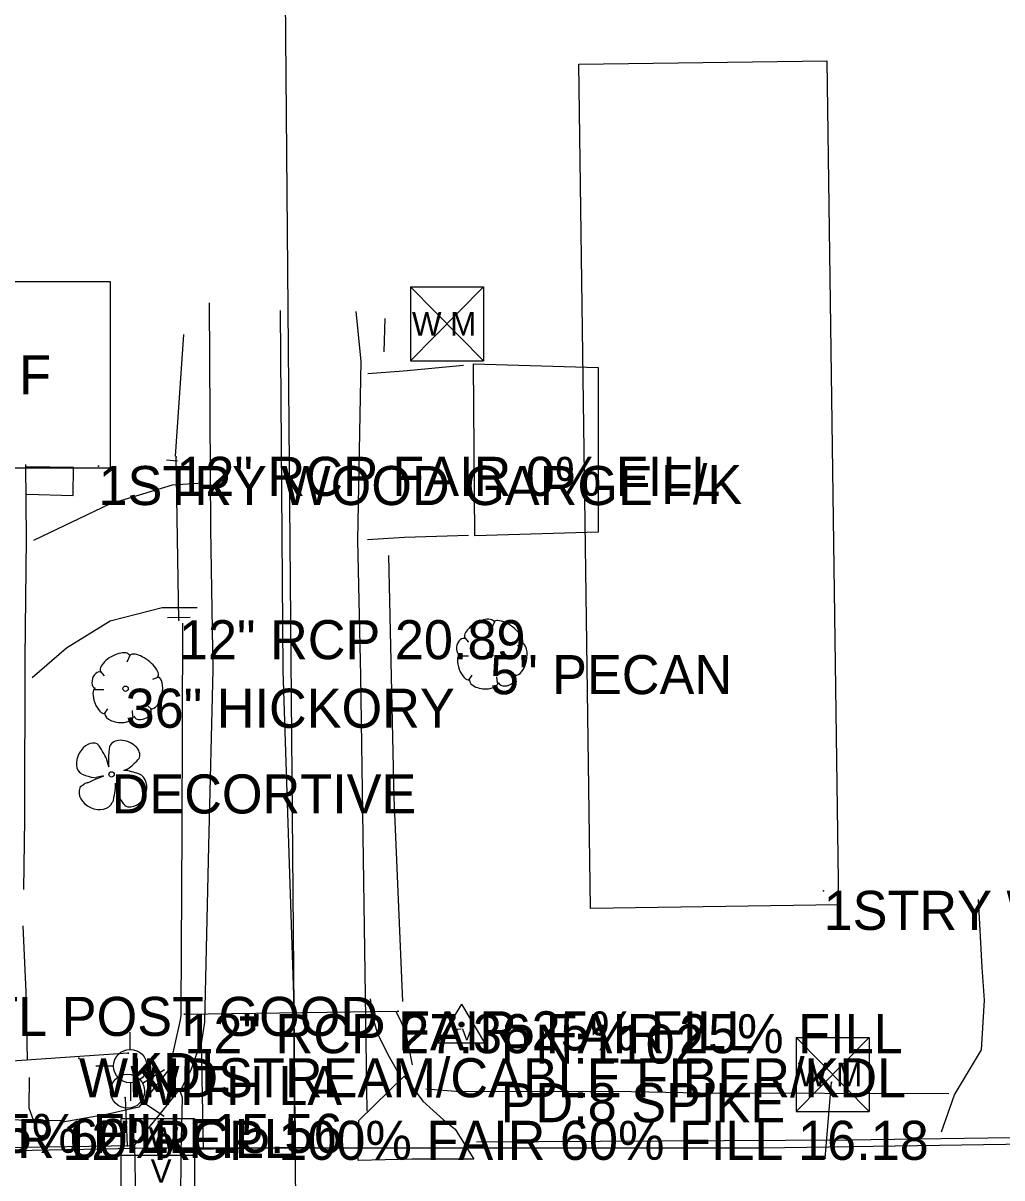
# Model space of a CAD drawing. Extents: x 1304270 to 1306561, y 1876019 to 1876752.
# Drawn here: x 1305592.5 to 1305717.8, y 1876418.6 to 1876566.4 of the extents above; entities that cross this region are included whole.
import ezdxf

# ---------------------------------------------------------------- set-up
doc = ezdxf.new("R2010")
doc.units = 0
for name, color, linetype in [('S_BUILDING', 7, 'Continuous'), ('S_BUILDING_ANNOT', 7, 'Continuous'), ('S_CROSS_DRAIN', 7, 'Continuous'), ('S_CROSS_DRAIN_ANNOT', 7, 'Continuous'), ('S_DITCHLINE', 7, 'Continuous'), ('S_DRG_PT_SYM', 7, 'Continuous'), ('S_DRIVEWAY', 7, 'Continuous'), ('S_EDGE_CONCRETE', 7, 'Continuous'), ('S_EDGE_PAVEMENT', 7, 'Continuous'), ('S_FENCE_ANNOT', 7, 'Continuous'), ('S_FIBER_OPTIC_CABLE', 7, 'Continuous'), ('S_FIBER_OPTIC_CABLE_ANNOT', 7, 'Continuous'), ('S_HEADWALL', 7, 'Continuous'), ('S_MSC_PT_SYM', 7, 'Continuous'), ('S_PAVEMENT_CROWN', 7, 'Continuous'), ('S_SANITARY_SEWER', 7, 'Continuous'), ('S_SECONDARY_CTL', 7, 'Continuous'), ('S_SECONDARY_CTL_ANNOT', 7, 'Continuous'), ('S_SHOULDER', 7, 'Continuous'), ('S_SIDE_DRAIN', 7, 'Continuous'), ('S_SIDE_DRAIN_ANNOT', 7, 'Continuous'), ('S_STR_PT_SYM', 7, 'Continuous'), ('S_SURVEY_TEXT_ANNOT', 7, 'Continuous'), ('S_TREE', 7, 'Continuous'), ('S_TREE_ANNOT', 7, 'Continuous'), ('S_UTILITY_POLE', 7, 'Continuous'), ('S_UTILITY_POLE_ANNOT', 7, 'Continuous'), ('S_UTL_PT_SYM', 7, 'Continuous'), ('S_WATER_UTILITIES', 7, 'Continuous')]:
    doc.layers.add(name, color=color, linetype=linetype)

msp = doc.modelspace()

# ---------------------------------------------------------------- linework, layer by layer
at = {"layer": 'S_BUILDING'}
for points in [[(1305695.38, 1876561.55), (1305696.88, 1876453.53), (1305665.14, 1876453.09), (1305663.64, 1876561.11)], [(1305583.2, 1876509.43), (1305583.21, 1876533.31), (1305603.68, 1876533.3), (1305603.67, 1876509.42)]]:
    msp.add_lwpolyline(points, close=True, dxfattribs=at)
at = {"layer": 'S_CROSS_DRAIN'}
msp.add_line((1305613.16, 1876439.55), (1305640.51, 1876439.91), dxfattribs=at)
at = {"layer": 'S_DITCHLINE'}
for points in [[(1305638.83, 1876528.57), (1305638.7, 1876524.33)], [(1305613.05, 1876526.51), (1305612, 1876510.94)], [(1305641.11, 1876441.17), (1305640.57, 1876454.2), (1305640.03, 1876467.24), (1305639.68, 1876482.75), (1305639.32, 1876498.26)], [(1305612.93, 1876489.58), (1305612.88, 1876476.34), (1305612.84, 1876463.1), (1305612.69, 1876440.08), (1305612.73, 1876439.33), (1305612.59, 1876438.62), (1305611.2, 1876432.5), (1305607.35, 1876427.64), (1305603.4, 1876426.75), (1305597.6, 1876425.74)], [(1305642.36, 1876433.06), (1305641.55, 1876437.08), (1305640.82, 1876438.78), (1305640.27, 1876439.83)]]:
    msp.add_lwpolyline(points, dxfattribs=at)
at = {"layer": 'S_DRG_PT_SYM'}
for points in [[(1305612.13, 1876510.88), (1305612.13, 1876510.93), (1305612.13, 1876510.88), (1305612.08, 1876510.88), (1305612.13, 1876510.88), (1305612.13, 1876510.83), (1305612.13, 1876510.88), (1305612.18, 1876510.88)], [(1305612.46, 1876489.97), (1305612.46, 1876490.02), (1305612.46, 1876489.97), (1305612.41, 1876489.97), (1305612.46, 1876489.97), (1305612.46, 1876489.92), (1305612.46, 1876489.97), (1305612.51, 1876489.97)], [(1305613.16, 1876439.55), (1305613.16, 1876439.6), (1305613.16, 1876439.55), (1305613.11, 1876439.55), (1305613.16, 1876439.55), (1305613.16, 1876439.5), (1305613.16, 1876439.55), (1305613.21, 1876439.55)], [(1305640.51, 1876439.91), (1305640.51, 1876439.96), (1305640.51, 1876439.91), (1305640.45, 1876439.91), (1305640.51, 1876439.91), (1305640.51, 1876439.86), (1305640.51, 1876439.91), (1305640.55, 1876439.91)], [(1305597.54, 1876425.9), (1305597.54, 1876425.95), (1305597.54, 1876425.9), (1305597.49, 1876425.9), (1305597.54, 1876425.9), (1305597.54, 1876425.85), (1305597.54, 1876425.9), (1305597.59, 1876425.9)]]:
    msp.add_lwpolyline(points, dxfattribs=at)
at = {"layer": 'S_DRIVEWAY'}
for points in [[(1305636.66, 1876521.54), (1305641.19, 1876521.88), (1305648.89, 1876522.59)], [(1305592.81, 1876509.9), (1305592.9, 1876500.39), (1305592.75, 1876485.12), (1305592.69, 1876464.5), (1305592.57, 1876455.51)], [(1305615.59, 1876507.51), (1305611.6, 1876507.24), (1305603.57, 1876504.81), (1305593.84, 1876500.18)], [(1305649.51, 1876500.8), (1305641.33, 1876500.55), (1305636.59, 1876500.27)], [(1305593.7, 1876482.62), (1305598.08, 1876486.44), (1305603.65, 1876489.87), (1305610.31, 1876491.59), (1305614.82, 1876491.57)], [(1305710.05, 1876424.49), (1305711.72, 1876429.21), (1305715.2, 1876434.98), (1305715.56, 1876441.35), (1305715.25, 1876445.5), (1305714.78, 1876454.23)], [(1305593.07, 1876433.69), (1305592.9, 1876442.34), (1305592.55, 1876450.85)], [(1305593.28, 1876431.42), (1305593.25, 1876427.54), (1305594.59, 1876423.91)]]:
    msp.add_lwpolyline(points, dxfattribs=at)
msp.add_lwpolyline([(1305650.18, 1876522.79), (1305666.13, 1876522.32), (1305666.14, 1876501.23), (1305650.34, 1876500.78)], close=True, dxfattribs=at)
at = {"layer": 'S_EDGE_CONCRETE'}
for points in [[(1305592.99, 1876506.09), (1305598.91, 1876505.92), (1305598.98, 1876509.5), (1305592.97, 1876509.58)], [(1305606.95, 1876415.73), (1305606.84, 1876422.83), (1305609.75, 1876426.4), (1305612.13, 1876429.33), (1305612.55, 1876429.88), (1305612.9, 1876428.9), (1305612.8, 1876425.2), (1305612.7, 1876421.97), (1305612.68, 1876415.16)]]:
    msp.add_lwpolyline(points, dxfattribs=at)
msp.add_lwpolyline([(1305650.19, 1876420.99), (1305642.3, 1876420.97), (1305635.39, 1876420.81), (1305635.48, 1876425.93), (1305641.29, 1876431.6), (1305643.69, 1876428.4), (1305646.34, 1876426.01), (1305647.82, 1876424.84)], close=True, dxfattribs=at)
at = {"layer": 'S_EDGE_PAVEMENT'}
for points in [[(1305615.62, 1876422.51), (1305615.36, 1876435.81), (1305615.78, 1876438.51), (1305616.3, 1876461.07), (1305616.83, 1876483.63), (1305616.55, 1876501.66), (1305616.47, 1876516.12), (1305616.39, 1876530.58)], [(1305636.55, 1876427.14), (1305636.35, 1876441.93), (1305636.05, 1876462.38), (1305635.75, 1876482.84), (1305635.35, 1876500.2), (1305635.78, 1876523.1), (1305635.13, 1876529.49)], [(1305640.77, 1876431.64), (1305639.41, 1876434.05), (1305637.97, 1876436.91), (1305637.33, 1876439), (1305636.97, 1876441.52)], [(1305612.66, 1876429.78), (1305614.03, 1876432.44), (1305615.18, 1876435.69)], [(1305650.55, 1876423.21), (1305674.32, 1876423.35), (1305698.09, 1876423.48), (1305721.97, 1876423.8), (1305745.85, 1876424.12), (1305770.29, 1876424.67), (1305794.74, 1876425.23), (1305811.42, 1876425.85), (1305825.07, 1876426.72), (1305843.96, 1876426.78), (1305860.03, 1876426.98), (1305876.09, 1876427.18), (1305883.24, 1876427.59), (1305898.06, 1876427.36), (1305904.05, 1876427.05), (1305918.23, 1876426.76), (1305933.32, 1876426.78)], [(1305388.38, 1876420.94), (1305412.9, 1876420.99), (1305437.42, 1876421.04), (1305451.62, 1876420.93), (1305465.15, 1876420.97), (1305478.67, 1876421.01), (1305492.19, 1876421.05), (1305505.71, 1876421.09), (1305520.11, 1876421.2), (1305523.54, 1876421.95), (1305534.76, 1876421.53), (1305559.32, 1876421.96), (1305583.88, 1876422.38), (1305606.66, 1876422.73)], [(1305612.81, 1876422.22), (1305627.2, 1876422.52), (1305635.24, 1876422.4)]]:
    msp.add_lwpolyline(points, dxfattribs=at)
at = {"layer": 'S_FIBER_OPTIC_CABLE'}
msp.add_line((1305605.99, 1876434.57), (1305581.98, 1876432.88), dxfattribs=at)
at = {"layer": 'S_HEADWALL'}
for points in [[(1305612.27, 1876510.3), (1305610.86, 1876510.44)], [(1305613.91, 1876490.33), (1305611, 1876490.27)]]:
    msp.add_lwpolyline(points, dxfattribs=at)
at = {"layer": 'S_MSC_PT_SYM'}
for points in [[(1305602.17, 1876509.7), (1305602.17, 1876509.75), (1305602.17, 1876509.7), (1305602.12, 1876509.7), (1305602.17, 1876509.7), (1305602.17, 1876509.65), (1305602.17, 1876509.7), (1305602.22, 1876509.7)], [(1305599.66, 1876433.91), (1305599.66, 1876433.96), (1305599.66, 1876433.91), (1305599.61, 1876433.91), (1305599.66, 1876433.91), (1305599.66, 1876433.86), (1305599.66, 1876433.91), (1305599.71, 1876433.91)]]:
    msp.add_lwpolyline(points, dxfattribs=at)
at = {"layer": 'S_PAVEMENT_CROWN'}
msp.add_lwpolyline([(1305627.31, 1876423.22), (1305627.18, 1876441.92), (1305626.49, 1876462.73), (1305625.8, 1876483.54), (1305625.64, 1876506.57), (1305625.48, 1876529.6)], dxfattribs=at)
at = {"layer": 'S_SANITARY_SEWER'}
msp.add_line((1305627.46, 1876413.95), (1305625.83, 1876600.63), dxfattribs=at)
at = {"layer": 'S_SECONDARY_CTL'}
for p, q in [((1305648.63, 1876440.83), (1305645.62, 1876435.88)), ((1305648.63, 1876440.83), (1305651.58, 1876435.88)), ((1305645.62, 1876435.88), (1305651.58, 1876435.88))]:
    msp.add_line(p, q, dxfattribs=at)
for radius in [0.311, 0.183, 0.103]:
    msp.add_circle((1305648.63, 1876438.22), radius, dxfattribs=at)
at = {"layer": 'S_SHOULDER'}
msp.add_lwpolyline([(1305644.05, 1876429.98), (1305648.45, 1876429.64), (1305668.23, 1876429.67), (1305679.16, 1876429.46), (1305695.09, 1876429.42), (1305711.02, 1876429.38)], dxfattribs=at)
at = {"layer": 'S_SIDE_DRAIN'}
for p, q in [((1305612.46, 1876489.97), (1305612.13, 1876510.88)), ((1305597.54, 1876425.9), (1305581.35, 1876426.14))]:
    msp.add_line(p, q, dxfattribs=at)
at = {"layer": 'S_STR_PT_SYM'}
msp.add_lwpolyline([(1305694.97, 1876455.33), (1305694.97, 1876455.38), (1305694.97, 1876455.33), (1305694.92, 1876455.33), (1305694.97, 1876455.33), (1305694.97, 1876455.28), (1305694.97, 1876455.33), (1305695.02, 1876455.33)], dxfattribs=at)
at = {"layer": 'S_TREE'}
for p, q in [((1305652.84, 1876489.74), (1305652.45, 1876488.89)), ((1305649.04, 1876487.73), (1305649.54, 1876487.15)), ((1305656.4, 1876486.95), (1305655.74, 1876486.68)), ((1305606.2, 1876485.44), (1305605.81, 1876484.59)), ((1305648.38, 1876485.4), (1305649.51, 1876485.4)), ((1305602.4, 1876483.43), (1305602.9, 1876482.85)), ((1305655.63, 1876482.85), (1305655.16, 1876483.27)), ((1305609.76, 1876482.65), (1305609.1, 1876482.38)), ((1305649.54, 1876482.23), (1305650.01, 1876482.92)), ((1305653.23, 1876481.96), (1305653.15, 1876482.73)), ((1305601.74, 1876481.1), (1305602.86, 1876481.1)), ((1305608.99, 1876478.55), (1305608.52, 1876478.97)), ((1305602.9, 1876477.93), (1305603.37, 1876478.62)), ((1305606.58, 1876477.65), (1305606.51, 1876478.43)), ((1305603.48, 1876471.21), (1305603.24, 1876472.1)), ((1305602.83, 1876470.05), (1305601.86, 1876469.83)), ((1305605.43, 1876470.75), (1305605.81, 1876470.91)), ((1305604.37, 1876469.12), (1305604.45, 1876468.68))]:
    msp.add_line(p, q, dxfattribs=at)
for centre in [(1305652.28, 1876485.5), (1305605.64, 1876481.2), (1305603.85, 1876470.23)]:
    msp.add_circle(centre, 0.341, dxfattribs=at)
for centre, major_axis, ratio, start_param, end_param in [((1305650.94, 1876488.7), (1.86, 1.08), 0.471018, 0, 3.141593), ((1305654.6, 1876488.38), (-1.81, 1.36), 0.405113, 3.141593, 6.283186), ((1305648.71, 1876486.59), (0.31, 1.03), 0.646762, 0, 3.141593), ((1305655.95, 1876484.97), (0.46, 2.04), 0.482994, 3.141593, 6.283185), ((1305604.3, 1876484.4), (1.86, 1.08), 0.471018, 0, 3.141593), ((1305607.96, 1876484.08), (-1.81, 1.36), 0.405113, 3.141593, 6.283186), ((1305649.01, 1876483.94), (-0.61, 1.6), 0.420543, 6.283185, 9.424777), ((1305602.07, 1876482.29), (0.31, 1.03), 0.646762, 0, 3.141593), ((1305609.31, 1876480.67), (0.46, 2.04), 0.482994, 3.141593, 6.283185), ((1305651.48, 1876482.16), (-1.83, 0.19), 0.529943, 0, 3.141593), ((1305654.43, 1876482.45), (1.09, 0.46), 0.711534, 3.141592, 6.283185), ((1305602.37, 1876479.64), (-0.61, 1.6), 0.420543, 6.283185, 9.424777), ((1305604.83, 1876477.85), (-1.83, 0.19), 0.529943, 0, 3.141593), ((1305607.79, 1876478.15), (1.09, 0.46), 0.711534, 3.141592, 6.283185), ((1305600.96, 1876472.25), (-1.03, -1.88), 0.662338, 3.141593, 6.283185), ((1305605.51, 1876473.12), (1.89, -0.74), 0.673998, 0, 3.141593), ((1305602.62, 1876473.12), (0.62, -1.01), 0.083512, 0, 3.141593), ((1305603.55, 1876472.54), (-0.07, -1.33), 0.068203, 3.141593, 6.283185), ((1305606.61, 1876471.64), (-0.798, -0.73), 0.092159, 0, 3.141593), ((1305600.9, 1876470.1), (0.964, -0.267), 0.113563, 3.141593, 6.283185), ((1305601.8, 1876469.61), (1.04, 0.44), 0.002756, 3.141593, 6.283185), ((1305606.39, 1876470.52), (0.96, -0.23), 0.056001, 0, 3.141593), ((1305606.47, 1876468.25), (0.88, 2.05), 0.81717, 3.141593, 6.283185), ((1305601.87, 1876467.57), (2.07, -0.93), 0.760068, 3.141593, 6.283185), ((1305600.28, 1876468.83), (0.477, 0.328), 0.136309, 0, 3.141593), ((1305604.13, 1876467.95), (0.19, 1.31), 0.114148, 3.141593, 5.822668), ((1305604.7, 1876467.91), (0.254, -0.771), 0.051603, 3.141593, 6.283185), ((1305605.28, 1876466.67), (-0.321, 0.467), 0.094289, 0, 3.141593)]:
    msp.add_ellipse(centre, major_axis=major_axis, ratio=ratio, start_param=start_param, end_param=end_param, dxfattribs=at)
at = {"layer": 'S_UTILITY_POLE'}
for p, q in [((1305606.24, 1876435.01), (1305606.24, 1876437.25)), ((1305604.15, 1876432.88), (1305601.82, 1876432.88)), ((1305606.32, 1876428.46), (1305606.32, 1876430.78))]:
    msp.add_line(p, q, dxfattribs=at)
msp.add_circle((1305606.24, 1876432.9), 2.13, dxfattribs=at)
at = {"layer": 'S_UTL_PT_SYM'}
for points in [[(1305605.99, 1876434.57), (1305605.99, 1876434.62), (1305605.99, 1876434.57), (1305605.94, 1876434.57), (1305605.99, 1876434.57), (1305605.99, 1876434.52), (1305605.99, 1876434.57), (1305606.04, 1876434.57)], [(1305695.99, 1876430.82), (1305695.99, 1876430.87), (1305695.99, 1876430.82), (1305695.94, 1876430.82), (1305695.99, 1876430.82), (1305695.99, 1876430.77), (1305695.99, 1876430.82), (1305696.04, 1876430.82)], [(1305605.6, 1876428.86), (1305605.6, 1876428.91), (1305605.6, 1876428.86), (1305605.55, 1876428.86), (1305605.6, 1876428.86), (1305605.6, 1876428.81), (1305605.6, 1876428.86), (1305605.65, 1876428.86)], [(1305605.86, 1876422.69), (1305605.86, 1876422.74), (1305605.86, 1876422.69), (1305605.81, 1876422.69), (1305605.86, 1876422.69), (1305605.86, 1876422.64), (1305605.86, 1876422.69), (1305605.91, 1876422.69)], [(1305609.14, 1876422.38), (1305609.14, 1876422.43), (1305609.14, 1876422.38), (1305609.09, 1876422.38), (1305609.14, 1876422.38), (1305609.14, 1876422.33), (1305609.14, 1876422.38), (1305609.19, 1876422.38)], [(1305687.16, 1876422.39), (1305687.16, 1876422.44), (1305687.16, 1876422.39), (1305687.11, 1876422.39), (1305687.16, 1876422.39), (1305687.16, 1876422.34), (1305687.16, 1876422.39), (1305687.21, 1876422.39)], [(1305695.18, 1876421.13), (1305695.18, 1876421.18), (1305695.18, 1876421.13), (1305695.13, 1876421.13), (1305695.18, 1876421.13), (1305695.18, 1876421.08), (1305695.18, 1876421.13), (1305695.23, 1876421.13)]]:
    msp.add_lwpolyline(points, dxfattribs=at)
at = {"layer": 'S_WATER_UTILITIES'}
for p, q in [((1305642.09, 1876532.64), (1305651.43, 1876532.64)), ((1305642.09, 1876532.64), (1305642.09, 1876523.14)), ((1305642.09, 1876532.64), (1305651.43, 1876523.14)), ((1305651.43, 1876532.64), (1305642.09, 1876523.14)), ((1305651.43, 1876532.64), (1305651.43, 1876523.14)), ((1305642.09, 1876523.14), (1305651.43, 1876523.14)), ((1305691.46, 1876436.56), (1305700.8, 1876436.56)), ((1305691.46, 1876436.56), (1305691.46, 1876427.07)), ((1305691.46, 1876436.56), (1305700.8, 1876427.07)), ((1305700.8, 1876436.56), (1305691.46, 1876427.07)), ((1305700.8, 1876436.56), (1305700.8, 1876427.07)), ((1305607.8, 1876430.73), (1305610.63, 1876432.46)), ((1305695.18, 1876421.13), (1305695.99, 1876430.82)), ((1305605.6, 1876428.86), (1305605.86, 1876422.69)), ((1305607.68, 1876428.42), (1305610.59, 1876426.5)), ((1305691.46, 1876427.07), (1305700.8, 1876427.07)), ((1305605.07, 1876426.2), (1305614.48, 1876426.2)), ((1305605.07, 1876416.79), (1305605.07, 1876426.2)), ((1305614.48, 1876426.2), (1305614.48, 1876416.79)), ((1305772.85, 1876423.7), (1305687.16, 1876422.39)), ((1305609.14, 1876422.38), (1305577.4, 1876421.77)), ((1305605.07, 1876421.51), (1305614.48, 1876421.51)), ((1305687.16, 1876422.39), (1305609.14, 1876422.38))]:
    msp.add_line(p, q, dxfattribs=at)
msp.add_circle((1305605.9, 1876429.68), 2.18, dxfattribs=at)

# ---------------------------------------------------------------- texts
at = {"layer": 'S_BUILDING_ANNOT'}
for s, p in [('F', (1305592, 1876518.87)), ('F/K', (1305674.16, 1876504.83)), ('1STRY WOOD', (1305694.97, 1876450.33))]:
    msp.add_text(s, height=5, dxfattribs=at).set_placement(p)
at = {"layer": 'S_CROSS_DRAIN_ANNOT'}
for s, p in [('12" RCP 27.36 FAIR 25% FILL', (1305613.16, 1876434.55)), ('FAIR 25% FILL', (1305640.51, 1876434.91))]:
    msp.add_text(s, height=5, dxfattribs=at).set_placement(p)
at = {"layer": 'S_FENCE_ANNOT'}
msp.add_text("3' CHAINLINK MTL POST GOOD", height=5, dxfattribs=at).set_placement((1305537.86, 1876436.76))
at = {"layer": 'S_FIBER_OPTIC_CABLE_ANNOT'}
msp.add_text('KDL', height=5, dxfattribs=at).set_placement((1305605.99, 1876429.57))
at = {"layer": 'S_SECONDARY_CTL'}
msp.add_text('TV', height=1.5, rotation=360, dxfattribs=at).set_placement((1305647.42, 1876436.21))
at = {"layer": 'S_SECONDARY_CTL_ANNOT'}
for s, p in [('PN:1102', (1305653.63, 1876433.22)), ('PD:8 SPIKE', (1305653.63, 1876425.72))]:
    msp.add_text(s, height=5, dxfattribs=at).set_placement(p)
at = {"layer": 'S_SIDE_DRAIN_ANNOT'}
for s, p in [('12" RCP FAIR 0% FILL', (1305612.13, 1876505.88)), ('12" RCP 20.89', (1305612.46, 1876484.97)), ('12" RCP POOR 85% FILL 15.56', (1305537.01, 1876421.79)), ('FAIR 60% FILL', (1305581.35, 1876421.14)), ('12" RCP 100% FAIR 60% FILL 16.18', (1305597.54, 1876420.9))]:
    msp.add_text(s, height=5, dxfattribs=at).set_placement(p)
at = {"layer": 'S_SURVEY_TEXT_ANNOT'}
for s, p in [('1STRY WOOD GARGE', (1305602.17, 1876504.7)), ('WINDSTREAM/CABLE FIBER/KDL', (1305599.66, 1876428.91))]:
    msp.add_text(s, height=5, dxfattribs=at).set_placement(p)
at = {"layer": 'S_TREE_ANNOT'}
for s, p in [('5" PECAN', (1305652.28, 1876480.5)), ('36" HICKORY', (1305605.64, 1876476.2)), ('DECORTIVE', (1305603.85, 1876465.23))]:
    msp.add_text(s, height=5, dxfattribs=at).set_placement(p)
at = {"layer": 'S_UTILITY_POLE_ANNOT'}
msp.add_text('WITH LA', height=5, dxfattribs=at).set_placement((1305606.24, 1876427.9))
at = {"layer": 'S_WATER_UTILITIES'}
for s, p in [('W M', (1305642.29, 1876526.4)), ('W M', (1305691.66, 1876430.33)), ('W', (1305608.62, 1876422.05)), ('V', (1305608.85, 1876417.98))]:
    msp.add_text(s, height=3, rotation=360, dxfattribs=at).set_placement(p)

doc.saveas('drawing.dxf')
